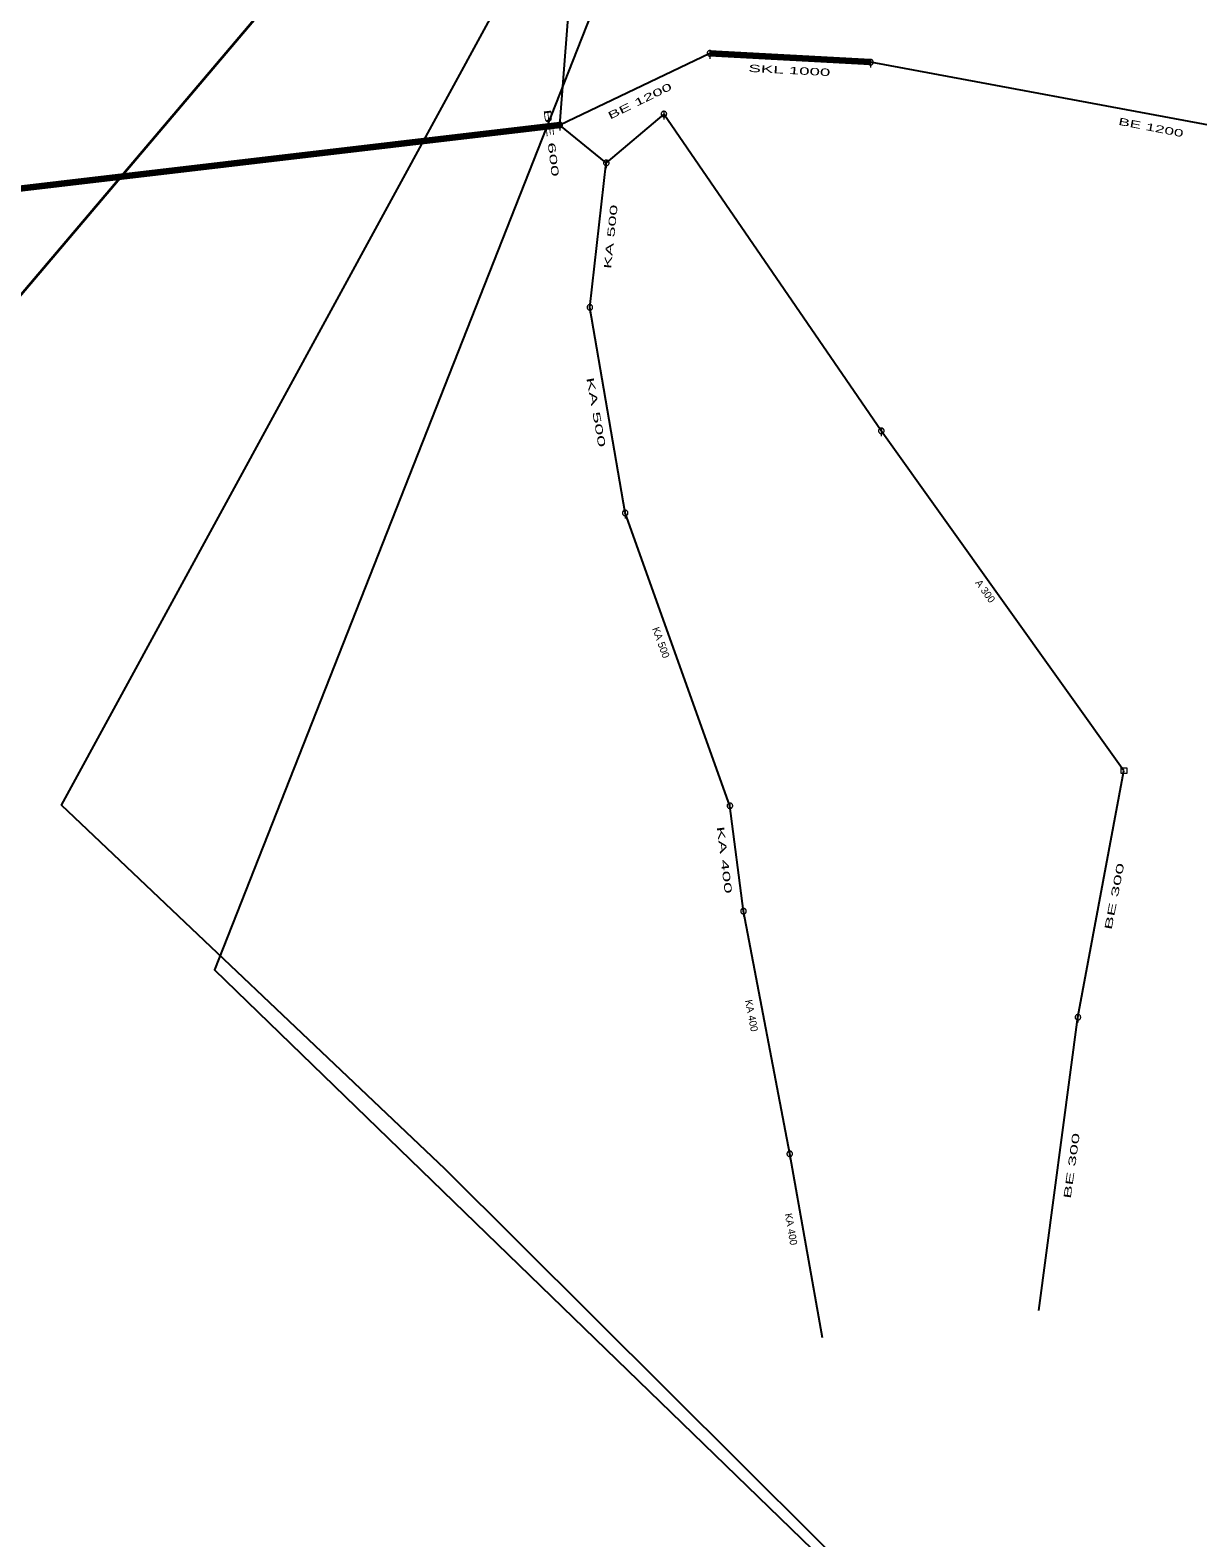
# Model space of a CAD drawing. Extents: x -687468 to -685917, y -974192 to -973456.
# Drawn here: x -686248.8 to -686142.7, y -974083.9 to -973947 of the extents above; entities that cross this region are included whole.
import ezdxf
from ezdxf.enums import TextEntityAlignment as Align

# ---------------------------------------------------------------- set-up
doc = ezdxf.new("R2010")
doc.units = 0
doc.header["$LTSCALE"] = 0.27
for name, color, linetype, lineweight in [('1', 7, 'Continuous', 13), ('14', 7, 'Continuous', 25), ('17', 7, 'Continuous', 25), ('2', 7, 'Continuous', 106), ('22', 7, 'Continuous', 13), ('27', 7, 'Continuous', 158)]:
    doc.layers.add(name, color=color, linetype=linetype, lineweight=lineweight)

msp = doc.modelspace()

# ---------------------------------------------------------------- linework, layer by layer
at = {"layer": '14'}
for p, q in [((-686172.417, -973949.902), (-686187.015, -973949.094)), ((-686120.612, -973959.55), (-686172.417, -973949.902)), ((-686191.19, -973954.607), (-686196.421, -973959.041)), ((-686171.44, -973983.379), (-686191.19, -973954.607)), ((-686200.654, -973955.608), (-686609.228, -974003.734)), ((-686196.422, -973959.042), (-686200.654, -973955.608)), ((-686149.399, -974014.248), (-686171.44, -973983.379)), ((-686185.193, -974017.434), (-686194.705, -973990.839)), ((-686183.962, -974027.006), (-686185.193, -974017.434)), ((-686179.761, -974049.043), (-686183.962, -974027.006)), ((-686176.788, -974065.77), (-686179.761, -974049.043))]:
    msp.add_line(p, q, dxfattribs=at)
for points in [[(-686187.015, -973949.094), (-686200.653, -973955.607), (-686199.917, -973946.239), (-686199.273, -973943.377)], [(-686194.705, -973990.839), (-686197.915, -973972.166), (-686196.422, -973959.042)], [(-686157.124, -974063.282), (-686153.58, -974036.639), (-686149.4, -974014.248)]]:
    msp.add_lwpolyline(points, dxfattribs=at)
at = {"layer": '17', "lineweight": 35}
msp.add_lwpolyline([(-686160.425, -973551.891), (-686169.469, -973574.282), (-686122.999, -973646.384), (-686098.932, -973712.353), (-686089.329, -973782.048), (-686297.791, -974027.806), (-686326.807, -974076.614), (-686379.703, -974100.561), (-686411.584, -974111.413)], dxfattribs=at)
at = {"layer": '17'}
for points in [[(-686144.92, -973826.734), (-686177.013, -973944.41), (-686197.048, -973943.572), (-686232.018, -974032.331), (-686151.042, -974110.8), (-686189.024, -974153.642), (-686204.782, -974140.962), (-686246.709, -974191.881)], [(-686150.349, -974110.866), (-686211.068, -974050.449), (-686245.909, -974017.381), (-686206.618, -973945.282), (-686204.755, -973943.783)]]:
    msp.add_lwpolyline(points, dxfattribs=at)
at = {"layer": '2'}
msp.add_line((-686172.417, -973949.902), (-686187.015, -973949.094), dxfattribs=at)
at = {"layer": '2', "lineweight": 100}
msp.add_line((-686172.417, -973949.902), (-686187.015, -973949.094), dxfattribs=at)
at = {"layer": '22'}
for p, q in [((-686187.014, -973948.842), (-686187.015, -973949.586)), ((-686172.416, -973949.65), (-686172.417, -973950.394)), ((-686200.653, -973955.356), (-686200.654, -973956.1)), ((-686191.189, -973954.355), (-686191.19, -973955.098)), ((-686196.421, -973958.79), (-686196.422, -973959.534)), ((-686197.914, -973971.914), (-686197.915, -973972.657)), ((-686171.439, -973983.127), (-686171.44, -973983.87)), ((-686194.704, -973990.587), (-686194.705, -973991.331)), ((-686185.192, -974017.182), (-686185.193, -974017.926)), ((-686183.961, -974026.754), (-686183.962, -974027.498)), ((-686153.579, -974036.387), (-686153.58, -974037.13)), ((-686179.76, -974048.791), (-686179.761, -974049.534))]:
    msp.add_line(p, q, dxfattribs=at)
for points in [[(-686186.763, -973949.094), (-686186.764, -973949.068), (-686186.768, -973949.042), (-686186.774, -973949.016), (-686186.784, -973948.992), (-686186.796, -973948.968), (-686186.81, -973948.946), (-686186.827, -973948.925), (-686186.845, -973948.907), (-686186.866, -973948.89), (-686186.888, -973948.876), (-686186.912, -973948.864), (-686186.936, -973948.854), (-686186.962, -973948.848), (-686186.988, -973948.844), (-686187.014, -973948.842), (-686187.04, -973948.843), (-686187.066, -973948.847), (-686187.092, -973948.853), (-686187.117, -973948.863), (-686187.14, -973948.875), (-686187.162, -973948.889), (-686187.183, -973948.906), (-686187.201, -973948.924), (-686187.218, -973948.945), (-686187.232, -973948.967), (-686187.244, -973948.991), (-686187.254, -973949.015), (-686187.261, -973949.041), (-686187.265, -973949.067), (-686187.267, -973949.093), (-686187.266, -973949.119), (-686187.262, -973949.145), (-686187.255, -973949.171), (-686187.245, -973949.196), (-686187.233, -973949.219), (-686187.219, -973949.241), (-686187.202, -973949.262), (-686187.184, -973949.28), (-686187.163, -973949.297), (-686187.141, -973949.311), (-686187.118, -973949.323), (-686187.093, -973949.333), (-686187.067, -973949.34), (-686187.041, -973949.344), (-686187.015, -973949.346), (-686186.989, -973949.345), (-686186.963, -973949.341), (-686186.937, -973949.334), (-686186.913, -973949.324), (-686186.889, -973949.312), (-686186.867, -973949.298), (-686186.846, -973949.281), (-686186.828, -973949.263), (-686186.811, -973949.242), (-686186.797, -973949.22), (-686186.785, -973949.197), (-686186.775, -973949.172), (-686186.769, -973949.146), (-686186.765, -973949.12)], [(-686172.165, -973949.902), (-686172.166, -973949.876), (-686172.17, -973949.85), (-686172.176, -973949.824), (-686172.186, -973949.8), (-686172.198, -973949.776), (-686172.212, -973949.754), (-686172.229, -973949.733), (-686172.247, -973949.715), (-686172.268, -973949.698), (-686172.29, -973949.684), (-686172.314, -973949.672), (-686172.338, -973949.662), (-686172.364, -973949.656), (-686172.39, -973949.652), (-686172.416, -973949.65), (-686172.442, -973949.651), (-686172.468, -973949.655), (-686172.494, -973949.661), (-686172.519, -973949.671), (-686172.542, -973949.683), (-686172.564, -973949.697), (-686172.585, -973949.714), (-686172.603, -973949.732), (-686172.62, -973949.753), (-686172.634, -973949.775), (-686172.646, -973949.799), (-686172.656, -973949.823), (-686172.663, -973949.849), (-686172.667, -973949.875), (-686172.669, -973949.901), (-686172.668, -973949.927), (-686172.664, -973949.953), (-686172.657, -973949.979), (-686172.647, -973950.004), (-686172.635, -973950.027), (-686172.621, -973950.049), (-686172.604, -973950.07), (-686172.586, -973950.088), (-686172.565, -973950.105), (-686172.543, -973950.119), (-686172.52, -973950.131), (-686172.495, -973950.141), (-686172.469, -973950.148), (-686172.443, -973950.152), (-686172.417, -973950.154), (-686172.391, -973950.153), (-686172.365, -973950.149), (-686172.339, -973950.142), (-686172.315, -973950.132), (-686172.291, -973950.12), (-686172.269, -973950.106), (-686172.248, -973950.089), (-686172.23, -973950.071), (-686172.213, -973950.05), (-686172.199, -973950.028), (-686172.187, -973950.005), (-686172.177, -973949.98), (-686172.171, -973949.954), (-686172.167, -973949.928)], [(-686200.402, -973955.608), (-686200.403, -973955.582), (-686200.407, -973955.556), (-686200.413, -973955.53), (-686200.423, -973955.506), (-686200.435, -973955.482), (-686200.449, -973955.46), (-686200.466, -973955.439), (-686200.484, -973955.421), (-686200.505, -973955.404), (-686200.527, -973955.39), (-686200.551, -973955.378), (-686200.575, -973955.368), (-686200.601, -973955.362), (-686200.627, -973955.358), (-686200.653, -973955.356), (-686200.679, -973955.357), (-686200.705, -973955.361), (-686200.731, -973955.367), (-686200.756, -973955.377), (-686200.779, -973955.389), (-686200.801, -973955.403), (-686200.822, -973955.42), (-686200.84, -973955.438), (-686200.857, -973955.459), (-686200.871, -973955.481), (-686200.883, -973955.505), (-686200.893, -973955.529), (-686200.9, -973955.555), (-686200.904, -973955.581), (-686200.906, -973955.607), (-686200.905, -973955.633), (-686200.901, -973955.659), (-686200.894, -973955.685), (-686200.884, -973955.71), (-686200.872, -973955.733), (-686200.858, -973955.755), (-686200.841, -973955.776), (-686200.823, -973955.794), (-686200.802, -973955.811), (-686200.78, -973955.825), (-686200.757, -973955.837), (-686200.732, -973955.847), (-686200.706, -973955.854), (-686200.68, -973955.858), (-686200.654, -973955.86), (-686200.628, -973955.859), (-686200.602, -973955.855), (-686200.576, -973955.848), (-686200.552, -973955.838), (-686200.528, -973955.826), (-686200.506, -973955.812), (-686200.485, -973955.795), (-686200.467, -973955.777), (-686200.45, -973955.756), (-686200.436, -973955.734), (-686200.424, -973955.711), (-686200.414, -973955.686), (-686200.408, -973955.66), (-686200.404, -973955.634)], [(-686190.938, -973954.607), (-686190.939, -973954.581), (-686190.943, -973954.555), (-686190.949, -973954.529), (-686190.959, -973954.505), (-686190.971, -973954.481), (-686190.985, -973954.459), (-686191.002, -973954.438), (-686191.02, -973954.42), (-686191.041, -973954.403), (-686191.063, -973954.389), (-686191.087, -973954.377), (-686191.111, -973954.367), (-686191.137, -973954.361), (-686191.163, -973954.357), (-686191.189, -973954.355), (-686191.215, -973954.356), (-686191.241, -973954.36), (-686191.267, -973954.366), (-686191.292, -973954.376), (-686191.315, -973954.388), (-686191.337, -973954.402), (-686191.358, -973954.419), (-686191.376, -973954.437), (-686191.393, -973954.458), (-686191.407, -973954.48), (-686191.419, -973954.504), (-686191.429, -973954.528), (-686191.436, -973954.554), (-686191.44, -973954.58), (-686191.441, -973954.606), (-686191.441, -973954.632), (-686191.437, -973954.658), (-686191.43, -973954.684), (-686191.42, -973954.709), (-686191.408, -973954.732), (-686191.394, -973954.754), (-686191.377, -973954.775), (-686191.359, -973954.793), (-686191.338, -973954.81), (-686191.316, -973954.824), (-686191.293, -973954.836), (-686191.268, -973954.846), (-686191.242, -973954.853), (-686191.216, -973954.857), (-686191.19, -973954.858), (-686191.164, -973954.858), (-686191.138, -973954.854), (-686191.112, -973954.847), (-686191.088, -973954.837), (-686191.064, -973954.825), (-686191.042, -973954.811), (-686191.021, -973954.794), (-686191.003, -973954.776), (-686190.986, -973954.755), (-686190.972, -973954.733), (-686190.96, -973954.71), (-686190.95, -973954.685), (-686190.944, -973954.659), (-686190.94, -973954.633)], [(-686196.17, -973959.042), (-686196.171, -973959.016), (-686196.175, -973958.99), (-686196.181, -973958.964), (-686196.191, -973958.94), (-686196.203, -973958.916), (-686196.217, -973958.894), (-686196.234, -973958.873), (-686196.252, -973958.855), (-686196.273, -973958.838), (-686196.295, -973958.824), (-686196.319, -973958.812), (-686196.343, -973958.802), (-686196.369, -973958.796), (-686196.395, -973958.792), (-686196.421, -973958.79), (-686196.447, -973958.791), (-686196.473, -973958.795), (-686196.499, -973958.801), (-686196.524, -973958.811), (-686196.547, -973958.823), (-686196.569, -973958.837), (-686196.59, -973958.854), (-686196.608, -973958.872), (-686196.625, -973958.893), (-686196.639, -973958.915), (-686196.651, -973958.939), (-686196.661, -973958.963), (-686196.668, -973958.989), (-686196.672, -973959.015), (-686196.674, -973959.041), (-686196.673, -973959.067), (-686196.669, -973959.093), (-686196.662, -973959.119), (-686196.652, -973959.144), (-686196.64, -973959.167), (-686196.626, -973959.189), (-686196.609, -973959.21), (-686196.591, -973959.228), (-686196.57, -973959.245), (-686196.548, -973959.259), (-686196.525, -973959.271), (-686196.5, -973959.281), (-686196.474, -973959.288), (-686196.448, -973959.292), (-686196.422, -973959.294), (-686196.396, -973959.293), (-686196.37, -973959.289), (-686196.344, -973959.282), (-686196.32, -973959.272), (-686196.296, -973959.26), (-686196.274, -973959.246), (-686196.253, -973959.229), (-686196.235, -973959.211), (-686196.218, -973959.19), (-686196.204, -973959.168), (-686196.192, -973959.145), (-686196.182, -973959.12), (-686196.176, -973959.094), (-686196.172, -973959.068)], [(-686197.663, -973972.166), (-686197.664, -973972.14), (-686197.668, -973972.114), (-686197.674, -973972.088), (-686197.684, -973972.064), (-686197.696, -973972.04), (-686197.71, -973972.018), (-686197.727, -973971.997), (-686197.745, -973971.979), (-686197.766, -973971.962), (-686197.788, -973971.948), (-686197.812, -973971.936), (-686197.836, -973971.926), (-686197.862, -973971.92), (-686197.888, -973971.916), (-686197.914, -973971.914), (-686197.94, -973971.915), (-686197.966, -973971.919), (-686197.992, -973971.925), (-686198.017, -973971.935), (-686198.04, -973971.947), (-686198.062, -973971.961), (-686198.083, -973971.978), (-686198.101, -973971.996), (-686198.118, -973972.017), (-686198.132, -973972.039), (-686198.144, -973972.063), (-686198.154, -973972.087), (-686198.161, -973972.113), (-686198.165, -973972.139), (-686198.167, -973972.165), (-686198.166, -973972.191), (-686198.162, -973972.217), (-686198.155, -973972.243), (-686198.145, -973972.268), (-686198.133, -973972.291), (-686198.119, -973972.313), (-686198.102, -973972.334), (-686198.084, -973972.352), (-686198.063, -973972.369), (-686198.041, -973972.383), (-686198.018, -973972.395), (-686197.993, -973972.405), (-686197.967, -973972.412), (-686197.941, -973972.416), (-686197.915, -973972.418), (-686197.889, -973972.417), (-686197.863, -973972.413), (-686197.837, -973972.406), (-686197.813, -973972.396), (-686197.789, -973972.384), (-686197.767, -973972.37), (-686197.746, -973972.353), (-686197.728, -973972.335), (-686197.711, -973972.314), (-686197.697, -973972.292), (-686197.685, -973972.269), (-686197.675, -973972.244), (-686197.669, -973972.218), (-686197.665, -973972.192)], [(-686171.188, -973983.379), (-686171.189, -973983.353), (-686171.193, -973983.327), (-686171.199, -973983.301), (-686171.209, -973983.277), (-686171.221, -973983.253), (-686171.235, -973983.231), (-686171.252, -973983.21), (-686171.27, -973983.192), (-686171.291, -973983.175), (-686171.313, -973983.161), (-686171.337, -973983.149), (-686171.361, -973983.139), (-686171.387, -973983.133), (-686171.413, -973983.129), (-686171.439, -973983.127), (-686171.465, -973983.128), (-686171.491, -973983.132), (-686171.517, -973983.138), (-686171.542, -973983.148), (-686171.565, -973983.16), (-686171.587, -973983.174), (-686171.608, -973983.191), (-686171.626, -973983.209), (-686171.643, -973983.23), (-686171.657, -973983.252), (-686171.669, -973983.276), (-686171.679, -973983.3), (-686171.686, -973983.326), (-686171.69, -973983.352), (-686171.691, -973983.378), (-686171.691, -973983.404), (-686171.687, -973983.43), (-686171.68, -973983.456), (-686171.67, -973983.481), (-686171.658, -973983.504), (-686171.644, -973983.526), (-686171.627, -973983.547), (-686171.609, -973983.565), (-686171.588, -973983.582), (-686171.566, -973983.596), (-686171.543, -973983.608), (-686171.518, -973983.618), (-686171.492, -973983.625), (-686171.466, -973983.629), (-686171.44, -973983.63), (-686171.414, -973983.63), (-686171.388, -973983.626), (-686171.362, -973983.619), (-686171.338, -973983.609), (-686171.314, -973983.597), (-686171.292, -973983.583), (-686171.271, -973983.566), (-686171.253, -973983.548), (-686171.236, -973983.527), (-686171.222, -973983.505), (-686171.21, -973983.482), (-686171.2, -973983.457), (-686171.194, -973983.431), (-686171.19, -973983.405)], [(-686194.453, -973990.839), (-686194.454, -973990.813), (-686194.458, -973990.787), (-686194.464, -973990.761), (-686194.474, -973990.737), (-686194.486, -973990.713), (-686194.5, -973990.691), (-686194.517, -973990.67), (-686194.535, -973990.652), (-686194.556, -973990.635), (-686194.578, -973990.621), (-686194.602, -973990.609), (-686194.626, -973990.599), (-686194.652, -973990.593), (-686194.678, -973990.589), (-686194.704, -973990.587), (-686194.73, -973990.588), (-686194.756, -973990.592), (-686194.782, -973990.598), (-686194.807, -973990.608), (-686194.83, -973990.62), (-686194.852, -973990.634), (-686194.873, -973990.651), (-686194.891, -973990.669), (-686194.908, -973990.69), (-686194.922, -973990.712), (-686194.934, -973990.736), (-686194.944, -973990.76), (-686194.951, -973990.786), (-686194.955, -973990.812), (-686194.956, -973990.838), (-686194.956, -973990.864), (-686194.952, -973990.89), (-686194.945, -973990.916), (-686194.935, -973990.941), (-686194.923, -973990.964), (-686194.909, -973990.986), (-686194.892, -973991.007), (-686194.874, -973991.025), (-686194.853, -973991.042), (-686194.831, -973991.056), (-686194.808, -973991.068), (-686194.783, -973991.078), (-686194.757, -973991.085), (-686194.731, -973991.089), (-686194.705, -973991.091), (-686194.679, -973991.09), (-686194.653, -973991.086), (-686194.627, -973991.079), (-686194.603, -973991.069), (-686194.579, -973991.057), (-686194.557, -973991.043), (-686194.536, -973991.026), (-686194.518, -973991.008), (-686194.501, -973990.987), (-686194.487, -973990.965), (-686194.475, -973990.942), (-686194.465, -973990.917), (-686194.459, -973990.891), (-686194.455, -973990.865)], [(-686149.648, -974014), (-686149.152, -974014), (-686149.152, -974014.496), (-686149.648, -974014.496)], [(-686184.941, -974017.434), (-686184.942, -974017.408), (-686184.946, -974017.382), (-686184.952, -974017.356), (-686184.962, -974017.332), (-686184.974, -974017.308), (-686184.988, -974017.286), (-686185.005, -974017.265), (-686185.023, -974017.247), (-686185.044, -974017.23), (-686185.066, -974017.216), (-686185.09, -974017.204), (-686185.114, -974017.194), (-686185.14, -974017.188), (-686185.166, -974017.184), (-686185.192, -974017.182), (-686185.218, -974017.183), (-686185.244, -974017.187), (-686185.27, -974017.193), (-686185.295, -974017.203), (-686185.318, -974017.215), (-686185.34, -974017.229), (-686185.361, -974017.246), (-686185.379, -974017.264), (-686185.396, -974017.285), (-686185.41, -974017.307), (-686185.422, -974017.331), (-686185.432, -974017.355), (-686185.439, -974017.381), (-686185.443, -974017.407), (-686185.445, -974017.433), (-686185.444, -974017.459), (-686185.44, -974017.485), (-686185.433, -974017.511), (-686185.423, -974017.536), (-686185.411, -974017.559), (-686185.397, -974017.581), (-686185.38, -974017.602), (-686185.362, -974017.62), (-686185.341, -974017.637), (-686185.319, -974017.651), (-686185.296, -974017.663), (-686185.271, -974017.673), (-686185.245, -974017.68), (-686185.219, -974017.684), (-686185.193, -974017.686), (-686185.167, -974017.685), (-686185.141, -974017.681), (-686185.115, -974017.674), (-686185.091, -974017.664), (-686185.067, -974017.652), (-686185.045, -974017.638), (-686185.024, -974017.621), (-686185.006, -974017.603), (-686184.989, -974017.582), (-686184.975, -974017.56), (-686184.963, -974017.537), (-686184.953, -974017.512), (-686184.947, -974017.486), (-686184.943, -974017.46)], [(-686183.71, -974027.006), (-686183.711, -974026.98), (-686183.715, -974026.954), (-686183.721, -974026.928), (-686183.731, -974026.904), (-686183.743, -974026.88), (-686183.757, -974026.858), (-686183.774, -974026.837), (-686183.792, -974026.819), (-686183.813, -974026.802), (-686183.835, -974026.788), (-686183.859, -974026.776), (-686183.883, -974026.766), (-686183.909, -974026.76), (-686183.935, -974026.756), (-686183.961, -974026.754), (-686183.987, -974026.755), (-686184.013, -974026.759), (-686184.039, -974026.765), (-686184.064, -974026.775), (-686184.087, -974026.787), (-686184.109, -974026.801), (-686184.13, -974026.818), (-686184.148, -974026.836), (-686184.165, -974026.857), (-686184.179, -974026.879), (-686184.191, -974026.903), (-686184.201, -974026.927), (-686184.208, -974026.953), (-686184.212, -974026.979), (-686184.214, -974027.005), (-686184.213, -974027.031), (-686184.209, -974027.057), (-686184.202, -974027.083), (-686184.192, -974027.108), (-686184.18, -974027.131), (-686184.166, -974027.153), (-686184.149, -974027.174), (-686184.131, -974027.192), (-686184.11, -974027.209), (-686184.088, -974027.223), (-686184.065, -974027.235), (-686184.04, -974027.245), (-686184.014, -974027.252), (-686183.988, -974027.256), (-686183.962, -974027.258), (-686183.936, -974027.257), (-686183.91, -974027.253), (-686183.884, -974027.246), (-686183.86, -974027.236), (-686183.836, -974027.224), (-686183.814, -974027.21), (-686183.793, -974027.193), (-686183.775, -974027.175), (-686183.758, -974027.154), (-686183.744, -974027.132), (-686183.732, -974027.109), (-686183.722, -974027.084), (-686183.716, -974027.058), (-686183.712, -974027.032)], [(-686153.328, -974036.639), (-686153.329, -974036.613), (-686153.333, -974036.587), (-686153.339, -974036.561), (-686153.349, -974036.537), (-686153.361, -974036.513), (-686153.375, -974036.491), (-686153.392, -974036.47), (-686153.41, -974036.452), (-686153.431, -974036.435), (-686153.453, -974036.421), (-686153.477, -974036.409), (-686153.501, -974036.399), (-686153.527, -974036.393), (-686153.553, -974036.389), (-686153.579, -974036.387), (-686153.605, -974036.388), (-686153.631, -974036.392), (-686153.657, -974036.398), (-686153.682, -974036.408), (-686153.705, -974036.42), (-686153.727, -974036.434), (-686153.748, -974036.451), (-686153.766, -974036.469), (-686153.783, -974036.49), (-686153.797, -974036.512), (-686153.809, -974036.536), (-686153.819, -974036.56), (-686153.826, -974036.586), (-686153.83, -974036.612), (-686153.831, -974036.638), (-686153.831, -974036.664), (-686153.827, -974036.69), (-686153.82, -974036.716), (-686153.81, -974036.741), (-686153.798, -974036.764), (-686153.784, -974036.786), (-686153.767, -974036.807), (-686153.749, -974036.825), (-686153.728, -974036.842), (-686153.706, -974036.856), (-686153.683, -974036.868), (-686153.658, -974036.878), (-686153.632, -974036.885), (-686153.606, -974036.889), (-686153.58, -974036.891), (-686153.554, -974036.89), (-686153.528, -974036.886), (-686153.502, -974036.879), (-686153.478, -974036.869), (-686153.454, -974036.857), (-686153.432, -974036.843), (-686153.411, -974036.826), (-686153.393, -974036.808), (-686153.376, -974036.787), (-686153.362, -974036.765), (-686153.35, -974036.742), (-686153.34, -974036.717), (-686153.334, -974036.691), (-686153.33, -974036.665)], [(-686179.509, -974049.043), (-686179.51, -974049.017), (-686179.514, -974048.991), (-686179.52, -974048.965), (-686179.53, -974048.941), (-686179.542, -974048.917), (-686179.556, -974048.895), (-686179.573, -974048.874), (-686179.591, -974048.856), (-686179.612, -974048.839), (-686179.634, -974048.825), (-686179.658, -974048.813), (-686179.682, -974048.803), (-686179.708, -974048.797), (-686179.734, -974048.793), (-686179.76, -974048.791), (-686179.786, -974048.792), (-686179.812, -974048.796), (-686179.838, -974048.802), (-686179.863, -974048.812), (-686179.886, -974048.824), (-686179.908, -974048.838), (-686179.929, -974048.855), (-686179.947, -974048.873), (-686179.964, -974048.894), (-686179.978, -974048.916), (-686179.99, -974048.94), (-686180, -974048.964), (-686180.007, -974048.99), (-686180.011, -974049.016), (-686180.013, -974049.042), (-686180.012, -974049.068), (-686180.008, -974049.094), (-686180.001, -974049.12), (-686179.991, -974049.145), (-686179.979, -974049.168), (-686179.965, -974049.19), (-686179.948, -974049.211), (-686179.93, -974049.229), (-686179.909, -974049.246), (-686179.887, -974049.26), (-686179.864, -974049.272), (-686179.839, -974049.282), (-686179.813, -974049.289), (-686179.787, -974049.293), (-686179.761, -974049.294), (-686179.735, -974049.294), (-686179.709, -974049.29), (-686179.683, -974049.283), (-686179.659, -974049.273), (-686179.635, -974049.261), (-686179.613, -974049.247), (-686179.592, -974049.23), (-686179.574, -974049.212), (-686179.557, -974049.191), (-686179.543, -974049.169), (-686179.531, -974049.146), (-686179.521, -974049.121), (-686179.515, -974049.095), (-686179.511, -974049.069)]]:
    msp.add_lwpolyline(points, close=True, dxfattribs=at)
at = {"layer": '27'}
msp.add_lwpolyline([(-686200.654, -973955.608), (-686609.228, -974003.734), (-687014.163, -974137.428)], dxfattribs=at)
msp.add_lwpolyline([(-686200.654, -973955.608), (-686609.228, -974003.734), (-687014.163, -974137.428)], dxfattribs=at)

# ---------------------------------------------------------------- texts
at = {"layer": '1'}
for s, rotation, width, p in [('SKL 1000', 357, 1.9, (-686179.809, -973950.968)), ('BE 1200 ', 26, 1.85, (-686193.027, -973953.625)), ('BE 600', 277, 2.1, (-686201.745, -973957.272)), ('BE 1200 ', 349, 1.75, (-686146.795, -973956.186)), ('KA 500', 84, 2, (-686195.693, -973965.787)), ('KA 500', 280, 2.2, (-686197.682, -973981.743)), ('KA 400', 277, 2.1, (-686186.023, -974022.394)), ('BE 300', 79, 2.1, (-686149.948, -974025.727)), ('BE 300', 82, 2.05, (-686153.826, -974050.175))]:
    msp.add_text(s, height=0.6667, rotation=rotation, dxfattribs=dict(at, width=width)).set_placement(p, align=Align.CENTER)
for s, rotation, p in [('A 300 ', 306, (-686162.196, -973998.234)), ('KA 500', 290, (-686191.769, -974002.719)), ('KA 400', 281, (-686183.554, -974036.554)), ('KA 400', 280, (-686179.961, -974055.943))]:
    msp.add_text(s, height=0.6667, rotation=rotation, dxfattribs=at).set_placement(p, align=Align.CENTER)

doc.saveas('drawing.dxf')
